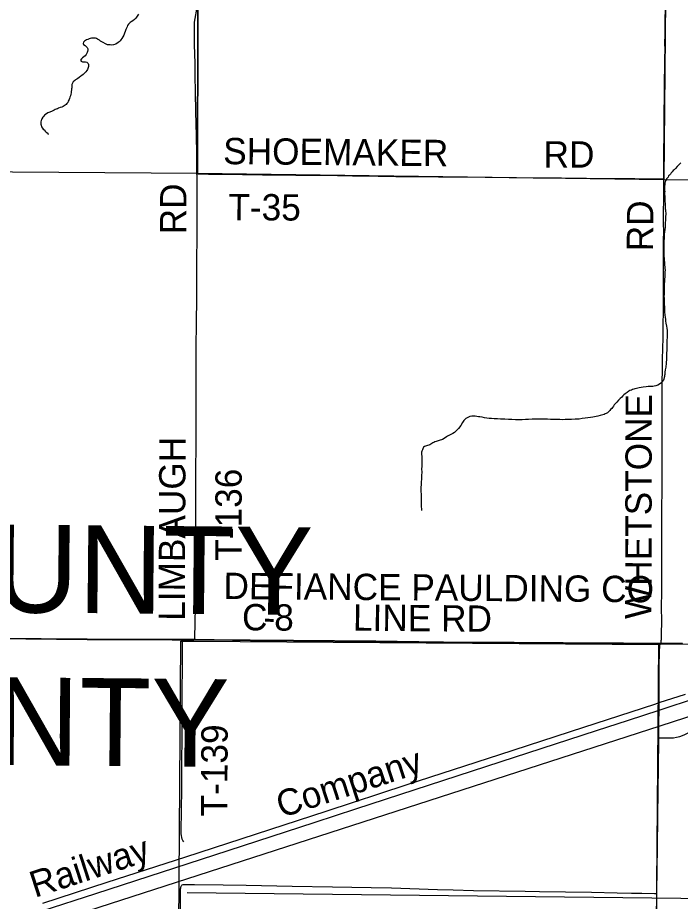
# Model space of a CAD drawing. Extents: x 2.4 to 73.1, y 4.5 to 25.6.
# Drawn here: x 32.327 to 33.042, y 21.341 to 22.294 of the extents above; entities that cross this region are included whole.
import ezdxf

# ---------------------------------------------------------------- set-up
doc = ezdxf.new("R2010")
doc.units = 0
for name, color, linetype in [('GM_X_County_Road', 7, 'Continuous'), ('GM_X_County_Road_Text', 7, 'Continuous'), ('GM_X_County_Text', 7, 'Continuous'), ('GM_X_Minor_River', 7, 'Continuous'), ('GM_X_Rail_Line', 7, 'Continuous'), ('GM_X_Rail_Line_Text', 7, 'Continuous'), ('GM_X_Section', 7, 'Continuous'), ('GM_X_Township', 7, 'Continuous'), ('GM_X_Township_Road', 7, 'Continuous'), ('GM_X_Township_Road_Text', 7, 'Continuous'), ('GM_X_US_Route', 7, 'Continuous'), ('SH_Cut_Line', 7, 'Continuous')]:
    doc.layers.add(name, color=color, linetype=linetype)

msp = doc.modelspace()

# ---------------------------------------------------------------- linework, layer by layer
at = {"layer": 'GM_X_County_Road'}
msp.add_line((32.5052, 21.6229), (32.51811, 21.62282), dxfattribs=at)
for points in [[(33.02436, 22.12034), (33.02435, 22.12228), (33.02437, 22.13408), (33.02432, 22.14061), (33.02442, 22.15305), (33.02456, 22.16455), (33.02467, 22.17729), (33.02486, 22.19159), (33.02497, 22.20899), (33.02506, 22.21676), (33.02509, 22.22547), (33.02538, 22.24101), (33.02561, 22.25531), (33.02561, 22.25996), (33.02559, 22.26618), (33.02573, 22.27613), (33.02582, 22.28514), (33.02609, 22.31001), (33.02646, 22.33395), (33.02651, 22.34203), (33.02657, 22.34887), (33.02658, 22.3585), (33.02647, 22.37223), (33.02645, 22.37476)], [(33.02085, 21.61856), (33.02097, 21.61901), (33.0213, 21.62051), (33.02154, 21.62192), (33.02169, 21.62326), (33.0218, 21.62533), (33.02184, 21.62862), (33.02203, 21.64323), (33.02198, 21.65753), (33.02217, 21.67494), (33.02225, 21.69608), (33.02228, 21.71131), (33.02207, 21.73339), (33.02222, 21.748), (33.02226, 21.76478), (33.02247, 21.78437), (33.02247, 21.79245), (33.02244, 21.8052), (33.0224, 21.81452), (33.02238, 21.82416), (33.02238, 21.83162), (33.02252, 21.85401), (33.02245, 21.86613), (33.02262, 21.90157), (33.02283, 21.91338), (33.02298, 21.92551), (33.02351, 21.94851), (33.02365, 21.96063), (33.02382, 21.97928), (33.02382, 21.99421), (33.02396, 22.02467), (33.02397, 22.03524), (33.02388, 22.0483), (33.02396, 22.05327), (33.02417, 22.06415), (33.02404, 22.07161), (33.02415, 22.08311), (33.0243, 22.09896), (33.02445, 22.10891), (33.02438, 22.11482), (33.02436, 22.12034)], [(32.51811, 21.62282), (32.51929, 21.62281), (32.53949, 21.62262), (32.57836, 21.62213), (32.625, 21.62167), (32.71362, 21.62098), (32.76026, 21.62025), (32.78669, 21.6199), (32.81778, 21.61967), (32.86287, 21.61955), (32.88463, 21.61933), (32.91572, 21.61916), (32.93749, 21.61892), (32.96236, 21.61886), (32.98102, 21.61887), (33.01651, 21.61863), (33.02085, 21.61856)], [(33.01916, 21.54701), (33.01916, 21.54756), (33.01921, 21.55501), (33.01943, 21.59265), (33.01984, 21.61131), (33.0199, 21.61496), (33.02001, 21.61612), (33.02014, 21.61687), (33.02038, 21.61765), (33.02085, 21.61856)], [(33.02085, 21.61856), (33.02249, 21.61855), (33.04476, 21.61844), (33.1054, 21.61773), (33.13457, 21.61727)], [(33.01906, 21.51698), (33.01908, 21.5258), (33.01907, 21.53357), (33.01916, 21.54701)], [(33.01681, 21.3492), (33.01713, 21.3766), (33.01745, 21.39836), (33.01799, 21.43254), (33.01905, 21.51337), (33.01906, 21.51698)], [(33.01432, 21.09649), (33.01438, 21.10239), (33.01506, 21.16984), (33.01564, 21.23513), (33.01595, 21.26623), (33.01616, 21.28954), (33.01639, 21.31286), (33.01681, 21.3492)]]:
    msp.add_lwpolyline(points, dxfattribs=at)
at = {"layer": 'GM_X_Minor_River'}
for points in [[(32.45759, 22.29787), (32.45463, 22.29339), (32.45326, 22.2919), (32.45171, 22.29061), (32.44978, 22.28952), (32.44862, 22.28879), (32.44765, 22.28787), (32.44687, 22.28694), (32.44569, 22.28545), (32.44528, 22.28432), (32.44467, 22.28281), (32.44387, 22.28113), (32.44326, 22.27924), (32.44245, 22.27736), (32.44183, 22.27529), (32.44083, 22.27342), (32.43983, 22.27154), (32.43866, 22.27005), (32.43787, 22.26912), (32.43671, 22.26801), (32.43555, 22.26709), (32.43304, 22.26564), (32.43055, 22.26475), (32.42864, 22.26442), (32.42713, 22.26465), (32.42431, 22.26462)], [(32.42431, 22.26462), (32.41751, 22.26829), (32.41676, 22.26868), (32.41563, 22.26965), (32.41431, 22.27043), (32.41337, 22.27101), (32.41242, 22.27141), (32.41129, 22.27181), (32.40977, 22.27183), (32.40844, 22.27185), (32.40692, 22.27188), (32.40558, 22.27152), (32.40443, 22.27115), (32.40309, 22.27061), (32.40156, 22.27006), (32.4006, 22.26932), (32.39945, 22.26857), (32.39829, 22.26764), (32.39808, 22.26612), (32.39844, 22.26498), (32.39994, 22.26401), (32.40107, 22.26304), (32.40219, 22.26169), (32.40293, 22.26054), (32.40291, 22.25921), (32.4027, 22.2575), (32.4023, 22.25656), (32.40191, 22.25561), (32.40132, 22.25448), (32.39996, 22.25279), (32.3988, 22.25186), (32.39726, 22.25056), (32.39611, 22.24963), (32.39513, 22.24831), (32.39587, 22.24697), (32.3972, 22.24657), (32.39815, 22.24655), (32.39967, 22.24653), (32.40062, 22.24651), (32.40195, 22.24611), (32.40325, 22.24457), (32.40381, 22.24342), (32.40378, 22.24152), (32.40258, 22.23831), (32.40181, 22.23718), (32.40083, 22.23568), (32.39948, 22.23418), (32.39793, 22.23269), (32.39658, 22.23157), (32.39543, 22.23082), (32.39369, 22.22933), (32.39216, 22.22841), (32.39101, 22.22767), (32.38985, 22.22692), (32.38889, 22.22637), (32.38735, 22.22487), (32.38637, 22.22337), (32.38578, 22.22186), (32.38556, 22.21977), (32.38573, 22.21844), (32.38552, 22.2173), (32.3853, 22.21559), (32.3851, 22.21465), (32.38488, 22.21313), (32.38467, 22.21162), (32.38426, 22.20972), (32.38366, 22.20821), (32.38326, 22.20689), (32.38286, 22.20575), (32.38188, 22.20387), (32.38129, 22.20255), (32.38032, 22.20142), (32.37955, 22.20049), (32.37839, 22.19956), (32.37743, 22.19881), (32.37628, 22.19807), (32.37494, 22.19752), (32.37322, 22.19698), (32.3715, 22.19624), (32.37015, 22.1957), (32.36882, 22.19534), (32.36767, 22.19497), (32.36652, 22.19442), (32.36441, 22.19332), (32.36192, 22.19222), (32.35982, 22.19149), (32.35731, 22.18944), (32.35635, 22.18869), (32.35558, 22.18776), (32.35442, 22.18663), (32.35344, 22.18494), (32.35304, 22.184), (32.35265, 22.18305), (32.35225, 22.18154), (32.35223, 22.1804), (32.3524, 22.17907), (32.35257, 22.17792), (32.35311, 22.1762), (32.35423, 22.17486), (32.35498, 22.1739), (32.35591, 22.17293)], [(32.35591, 22.17293), (32.35704, 22.17177), (32.35816, 22.17061), (32.3591, 22.16965), (32.36022, 22.1683), (32.36041, 22.1683)], [(33.04275, 22.1376), (33.04176, 22.13629), (33.04021, 22.13481), (33.03865, 22.13333), (33.03709, 22.13147), (33.03534, 22.13), (33.03437, 22.12926), (33.03319, 22.12758), (33.03221, 22.12647), (33.03142, 22.12516), (33.03044, 22.12404), (33.02947, 22.12331), (33.02887, 22.122), (33.0279, 22.12107), (33.02731, 22.12014), (33.0269, 22.1192), (33.0263, 22.11807), (33.0259, 22.11713), (33.02548, 22.11563), (33.02526, 22.11411), (33.02521, 22.11221), (33.0251, 22.10804), (33.02526, 22.10652), (33.02523, 22.10557), (33.02521, 22.10462), (33.02518, 22.10329), (33.02532, 22.10157), (33.02547, 22.10005), (33.02542, 22.09797), (33.02556, 22.09587), (33.02569, 22.09359), (33.02583, 22.09131), (33.02578, 22.0896), (33.02593, 22.08789), (33.02609, 22.08655), (33.02624, 22.08503), (33.02639, 22.08332), (33.02634, 22.08161), (33.0263, 22.0799), (33.02626, 22.07819), (33.02622, 22.07667), (33.02599, 22.07497), (33.02595, 22.07345), (33.02571, 22.07156), (33.02567, 22.06966), (33.02562, 22.06795), (33.02537, 22.0653), (33.02512, 22.06303), (33.02487, 22.06057), (33.02481, 22.0581), (33.02455, 22.05564), (33.02449, 22.05317), (33.02444, 22.05089), (33.02419, 22.04843), (33.02433, 22.04653), (33.02427, 22.04406), (33.02439, 22.04159), (33.02434, 22.03931), (33.02446, 22.03646), (33.0246, 22.03475), (33.02457, 22.03342), (33.02472, 22.03189), (33.02488, 22.03056), (33.02503, 22.02885), (33.02517, 22.02694), (33.02532, 22.02523), (33.02546, 22.02352), (33.0256, 22.02162), (33.02537, 22.01972), (33.02549, 22.01706), (33.02511, 22.00928), (33.02485, 22.00663), (33.02478, 22.00398), (33.02472, 22.00151), (33.02465, 21.99866), (33.02458, 21.99581), (33.02451, 21.99316), (33.02466, 21.99125), (33.02479, 21.98916), (33.02473, 21.98669), (33.02487, 21.98441), (33.02501, 21.9827), (33.02496, 21.98061)], [(33.02496, 21.98061), (33.0251, 21.97871), (33.02504, 21.97624), (33.02535, 21.97338), (33.02566, 21.97072), (33.026, 21.96881), (33.02613, 21.96672), (33.02665, 21.96443), (33.02714, 21.96138), (33.02765, 21.95889), (33.02797, 21.95661), (33.02811, 21.95451), (33.02806, 21.95262), (33.02801, 21.95053), (33.02777, 21.94845), (33.02772, 21.94655), (33.02766, 21.94408), (33.0276, 21.9418), (33.02754, 21.93953), (33.0275, 21.93763), (33.02742, 21.93478), (33.02738, 21.93288), (33.02733, 21.93099), (33.02727, 21.92871), (33.02721, 21.92605), (33.0269, 21.92131), (33.02641, 21.91695), (33.02595, 21.91393), (33.02551, 21.91147), (33.02527, 21.9092), (33.02504, 21.90787), (33.02501, 21.90674), (33.02461, 21.9058), (33.02419, 21.9041), (33.02357, 21.90221), (33.0226, 21.9011), (33.02123, 21.89961), (33.01949, 21.89852), (33.01775, 21.89742), (33.01565, 21.89672), (33.01393, 21.89638), (33.0126, 21.89622), (33.01165, 21.89625), (33.01051, 21.89628), (33.00917, 21.89612), (33.00746, 21.89597), (33.00517, 21.89565), (33.00194, 21.89535), (32.99984, 21.89503), (32.99774, 21.8947), (32.99622, 21.89436), (32.99488, 21.89401), (32.99316, 21.89368), (32.99182, 21.89314), (32.99067, 21.89279), (32.98933, 21.89226), (32.98779, 21.89172), (32.98664, 21.89099), (32.9847, 21.88952), (32.98277, 21.88824), (32.98122, 21.88714), (32.98025, 21.88622), (32.97888, 21.88473), (32.97713, 21.88307), (32.97538, 21.88121), (32.97381, 21.87935), (32.97225, 21.87768), (32.97088, 21.8762), (32.9699, 21.8749), (32.96911, 21.87359), (32.96813, 21.87247), (32.96696, 21.87117), (32.96598, 21.87006), (32.96481, 21.86895), (32.96345, 21.86765), (32.9623, 21.86711), (32.96115, 21.86657), (32.9598, 21.86604), (32.95559, 21.86481), (32.9533, 21.86411), (32.94776, 21.86311), (32.94529, 21.86279), (32.93957, 21.86199), (32.93633, 21.86169), (32.93309, 21.86101), (32.92853, 21.86094), (32.92472, 21.86066), (32.9213, 21.86055), (32.91788, 21.86045), (32.91502, 21.86014), (32.91199, 21.86041), (32.90876, 21.86049), (32.90535, 21.86058), (32.90193, 21.86066), (32.8989, 21.86093), (32.89605, 21.861), (32.89225, 21.86091), (32.88921, 21.86098), (32.88541, 21.86089), (32.88219, 21.86097), (32.87838, 21.86069)], [(32.87838, 21.86069), (32.87495, 21.8604), (32.87134, 21.8603), (32.86792, 21.86019), (32.86432, 21.86028), (32.86052, 21.86038), (32.85672, 21.86048), (32.85293, 21.86076), (32.84819, 21.86088), (32.84477, 21.86116), (32.84136, 21.86125), (32.83833, 21.86151), (32.83586, 21.86176), (32.8334, 21.86202), (32.83094, 21.86246), (32.82829, 21.8629), (32.82603, 21.86334), (32.82451, 21.86357), (32.82262, 21.86381), (32.82073, 21.86405), (32.81978, 21.86407), (32.81845, 21.8641), (32.81711, 21.86395), (32.81521, 21.86362), (32.81367, 21.86308), (32.81214, 21.86236), (32.81078, 21.86145), (32.80962, 21.86053), (32.80864, 21.85941), (32.80726, 21.85717), (32.80528, 21.85399), (32.80292, 21.85063), (32.79864, 21.84656), (32.79671, 21.84528), (32.79459, 21.8442), (32.79093, 21.84239), (32.78997, 21.84165), (32.78842, 21.84074), (32.78572, 21.8391), (32.78189, 21.83768), (32.77883, 21.83681), (32.77749, 21.83646), (32.77614, 21.83574), (32.77518, 21.83519), (32.77402, 21.83446), (32.77209, 21.83318), (32.76845, 21.83194), (32.76616, 21.83124), (32.76519, 21.83051), (32.76439, 21.82882), (32.76398, 21.82788), (32.76337, 21.82638), (32.76297, 21.82525), (32.76294, 21.82411), (32.7631, 21.82277), (32.76324, 21.82087), (32.7632, 21.81916), (32.76335, 21.81764), (32.7633, 21.81555), (32.76325, 21.81384), (32.7632, 21.81195), (32.76315, 21.80986), (32.76309, 21.80739), (32.76319, 21.80378), (32.7631, 21.80017), (32.76282, 21.79638), (32.76273, 21.79297), (32.76247, 21.79012), (32.76221, 21.78747), (32.76213, 21.78425), (32.76228, 21.78234), (32.76241, 21.78025), (32.76254, 21.77778), (32.76247, 21.77474), (32.76259, 21.77208), (32.76253, 21.76961), (32.76266, 21.76714), (32.76276, 21.76353), (32.76292, 21.76239)], [(32.50998, 21.35024), (33.07394, 21.34372), (33.14382, 21.39998), (33.14632, 21.41556), (33.1498, 21.45015), (33.15704, 21.46115), (33.16712, 21.46493), (33.3527, 21.46383), (33.38617, 21.46621), (33.42042, 21.47866), (33.44591, 21.48372), (33.47044, 21.48441), (33.5127, 21.49167)]]:
    msp.add_lwpolyline(points, dxfattribs=at)
at = {"layer": 'GM_X_Rail_Line'}
msp.add_lwpolyline([(29.49738, 20.38454), (29.78056, 20.47623), (30.02642, 20.55584), (30.5317, 20.7222), (31.06173, 20.89547), (31.60226, 21.07108), (31.99378, 21.19809), (32.24901, 21.28076), (33.02045, 21.53011), (33.27514, 21.61267)], dxfattribs=at)
at = {"layer": 'GM_X_Section'}
for points in [[(32.52237, 22.62648), (32.5213, 22.12602), (32.02184, 22.12942), (32.0257, 22.62946)], [(33.02904, 22.62432), (33.02446, 22.1192), (32.5213, 22.12602), (32.52237, 22.62648)], [(33.5389, 22.62058), (33.53887, 22.61906), (33.53166, 22.11533), (33.02446, 22.1192), (33.02904, 22.62432)], [(32.51749, 21.62129), (33.01863, 21.61775), (33.01442, 21.09688), (32.49959, 21.10721), (32.50347, 21.62138)]]:
    msp.add_lwpolyline(points, close=True, dxfattribs=at)
at = {"layer": 'GM_X_Township'}
msp.add_lwpolyline([(32.30268, 21.62435), (32.40211, 21.6236), (32.45338, 21.62327), (32.49377, 21.62322), (32.50508, 21.62318), (32.51799, 21.62309), (32.51917, 21.62308), (32.53937, 21.6229), (32.57824, 21.6224), (32.62488, 21.62194), (32.7135, 21.62126), (32.76014, 21.62052), (32.78657, 21.62018), (32.81766, 21.61995), (32.86275, 21.61982), (32.88451, 21.6196), (32.91561, 21.61943), (32.93737, 21.61919), (32.96224, 21.61913), (32.9809, 21.61915), (33.01639, 21.61891), (33.02074, 21.61883), (33.02237, 21.61883), (33.04465, 21.61871)], dxfattribs=at)
msp.add_lwpolyline([(32.30268, 21.62435), (32.40211, 21.6236), (32.45338, 21.62327), (32.49377, 21.62322), (32.50508, 21.62318), (32.51799, 21.62309), (32.51917, 21.62308), (32.53937, 21.6229), (32.57824, 21.6224), (32.62488, 21.62194), (32.7135, 21.62126), (32.76014, 21.62052), (32.78657, 21.62018), (32.81766, 21.61995), (32.86275, 21.61982), (32.88451, 21.6196), (32.91561, 21.61943), (32.93737, 21.61919), (32.96224, 21.61913), (32.9809, 21.61915), (33.01639, 21.61891), (33.02074, 21.61883), (33.02237, 21.61883), (33.04465, 21.61871)], dxfattribs=at)
at = {"layer": 'GM_X_Township_Road'}
msp.add_line((32.5052, 21.6229), (32.51811, 21.62282), dxfattribs=at)
for points in [[(32.52073, 22.12551), (32.52061, 22.1333), (32.52042, 22.14698), (32.52005, 22.16656), (32.51945, 22.19297), (32.51923, 22.21348), (32.51887, 22.23213), (32.5187, 22.24487), (32.51823, 22.26475), (32.51807, 22.27439), (32.51797, 22.28309), (32.51807, 22.28713), (32.51823, 22.28929), (32.51872, 22.29298), (32.52041, 22.3031)], [(32.51811, 21.62282), (32.51825, 21.62463), (32.51833, 21.62736), (32.51866, 21.63864), (32.51876, 21.64216), (32.5188, 21.64429), (32.51898, 21.65505), (32.51914, 21.66678), (32.51913, 21.69507), (32.51945, 21.73018), (32.51954, 21.77215), (32.51965, 21.79856), (32.51976, 21.83959), (32.51985, 21.85544), (32.51992, 21.87347), (32.51991, 21.89119), (32.51994, 21.91201), (32.51995, 21.93843), (32.52017, 21.96454), (32.5205, 21.99127), (32.5206, 22.03789), (32.52081, 22.05156), (32.52083, 22.08047), (32.52096, 22.10161), (32.5208, 22.1199)], [(32.52073, 22.12551), (32.5243, 22.12548), (32.52555, 22.12548), (32.53332, 22.12526), (32.54296, 22.12507), (32.57, 22.12478), (32.59146, 22.12458), (32.62721, 22.12419), (32.63592, 22.12412), (32.6468, 22.12409), (32.67229, 22.12367), (32.68846, 22.1235), (32.7012, 22.12331), (32.71612, 22.12322), (32.7354, 22.12287), (32.74908, 22.12269), (32.76649, 22.12256), (32.78142, 22.12248), (32.79323, 22.12236), (32.83178, 22.1219), (32.88339, 22.12132), (32.89738, 22.12126), (32.91386, 22.12115), (32.94091, 22.12094), (32.97324, 22.1206), (32.99314, 22.12049), (33.01211, 22.12028), (33.0205, 22.12032), (33.02436, 22.12034)], [(32.5208, 22.1199), (32.52077, 22.12336), (32.52073, 22.12551)], [(32.01559, 21.62599), (32.04024, 21.62583), (32.05733, 21.62573), (32.08374, 21.62554), (32.10394, 21.62554), (32.14277, 21.62518), (32.17851, 21.62504), (32.20337, 21.62488), (32.24842, 21.62448), (32.2624, 21.62439), (32.2826, 21.62423), (32.3028, 21.62407), (32.40223, 21.62332), (32.4535, 21.623), (32.49389, 21.62295), (32.5052, 21.6229)], [(32.50661, 21.40479), (32.50541, 21.40642), (32.50473, 21.40773), (32.50427, 21.40964), (32.50386, 21.4118), (32.50375, 21.41336), (32.50385, 21.42065), (32.50404, 21.43418), (32.5043, 21.46681), (32.50439, 21.49324), (32.50459, 21.515), (32.50463, 21.54763), (32.50482, 21.56006), (32.50507, 21.60047), (32.5052, 21.6229)], [(32.51811, 21.62282), (32.51929, 21.62281), (32.53949, 21.62262), (32.57836, 21.62213), (32.625, 21.62167), (32.71362, 21.62098), (32.76026, 21.62025), (32.78669, 21.6199), (32.81778, 21.61967), (32.86287, 21.61955), (32.88463, 21.61933), (32.91572, 21.61916), (32.93749, 21.61892), (32.96236, 21.61886), (32.98102, 21.61887), (33.01651, 21.61863), (33.02085, 21.61856)], [(33.01906, 21.51698), (33.0225, 21.51698), (33.03181, 21.51699), (33.03488, 21.51721), (33.03791, 21.51765), (33.04177, 21.51862), (33.04637, 21.52038), (33.05131, 21.52292), (33.05985, 21.52798), (33.06978, 21.53383), (33.0764, 21.53734), (33.08233, 21.54012), (33.08837, 21.54263), (33.09627, 21.54552), (33.11635, 21.55218), (33.15567, 21.56499), (33.2553, 21.59744), (33.28546, 21.60725), (33.29385, 21.60965), (33.30113, 21.61141), (33.30848, 21.61279), (33.31528, 21.6137), (33.32274, 21.61432), (33.33053, 21.61456)], [(33.02085, 21.61856), (33.02249, 21.61855), (33.04476, 21.61844), (33.1054, 21.61773), (33.13457, 21.61727)], [(32.50074, 21.10816), (32.50069, 21.11094), (32.50136, 21.15601), (32.50145, 21.17311), (32.50189, 21.21973), (32.50222, 21.24304), (32.50216, 21.24926), (32.50236, 21.2679), (32.50276, 21.28811), (32.50295, 21.31142), (32.50305, 21.33784), (32.50305, 21.35248), (32.50307, 21.35327), (32.5031, 21.35415), (32.50318, 21.35529), (32.50326, 21.3562), (32.50352, 21.35695), (32.50393, 21.35756)], [(32.50393, 21.35756), (32.50436, 21.35805), (32.50487, 21.35843), (32.50566, 21.35871), (32.50653, 21.35878), (32.50862, 21.35879), (32.51793, 21.35866), (32.54896, 21.35855), (32.57379, 21.35809), (32.62344, 21.35687), (32.66688, 21.35631), (32.70878, 21.35548), (32.7305, 21.35514), (32.78014, 21.3536), (32.79719, 21.35293), (32.81891, 21.35221), (32.87477, 21.35149), (32.89029, 21.35123), (32.91822, 21.35094), (32.94615, 21.35039), (32.97407, 21.34966), (32.98959, 21.34942), (33.00045, 21.34945), (33.01441, 21.34924), (33.01681, 21.3492)]]:
    msp.add_lwpolyline(points, dxfattribs=at)
at = {"layer": 'GM_X_US_Route'}
for points in [[(32.35363, 21.33033), (32.41155, 21.34922), (32.55434, 21.39562), (32.64833, 21.42624), (32.69207, 21.44047), (32.724, 21.45084), (32.83338, 21.4864), (32.95188, 21.52506), (32.98617, 21.53622), (33.01916, 21.54701), (33.03344, 21.55168), (33.12659, 21.58187)], [(32.35445, 21.33859), (32.42392, 21.36119), (32.46617, 21.375), (32.50874, 21.38884), (32.66009, 21.43808), (32.74757, 21.46659), (32.84748, 21.49912), (32.93821, 21.52867), (33.01449, 21.55346), (33.01921, 21.55501), (33.04757, 21.56429)]]:
    msp.add_lwpolyline(points, dxfattribs=at)
at = {"layer": 'SH_Cut_Line'}
for points in [[(33.04465, 21.61871), (33.02237, 21.61883), (33.02074, 21.61883), (33.01639, 21.61891), (32.9809, 21.61915), (32.96224, 21.61913), (32.93737, 21.61919), (32.91561, 21.61943), (32.88451, 21.6196), (32.86275, 21.61982), (32.81766, 21.61995), (32.78657, 21.62018), (32.76014, 21.62052), (32.7135, 21.62126), (32.62488, 21.62194), (32.57824, 21.6224), (32.53937, 21.6229), (32.51917, 21.62308), (32.51799, 21.62309), (32.50508, 21.62318), (32.49377, 21.62322), (32.45338, 21.62327), (32.40211, 21.6236), (32.30268, 21.62435)], [(32.30268, 21.62435), (32.40211, 21.6236), (32.45338, 21.62327), (32.49377, 21.62322), (32.50508, 21.62318), (32.51799, 21.62309), (32.51917, 21.62308), (32.53937, 21.6229), (32.57824, 21.6224), (32.62488, 21.62194), (32.7135, 21.62126), (32.76014, 21.62052), (32.78657, 21.62018), (32.81766, 21.61995), (32.86275, 21.61982), (32.88451, 21.6196), (32.91561, 21.61943), (32.93737, 21.61919), (32.96224, 21.61913), (32.9809, 21.61915), (33.01639, 21.61891), (33.02074, 21.61883), (33.02237, 21.61883), (33.04465, 21.61871)]]:
    msp.add_lwpolyline(points, dxfattribs=at)

# ---------------------------------------------------------------- texts
at = {"layer": 'GM_X_County_Road_Text'}
for s, height, rotation, p in [('RD', 0.028409, 89.51079, (33.01265, 22.04189)), ('WHETSTONE', 0.028409, 89.88753, (33.01097, 21.64528)), ('DEFIANCE PAULDING CO', 0.0284091, 359.54135, (32.54926, 21.6669)), ('C', 0.02841, 359.44721, (32.5692, 21.63315)), ('8', 0.02841, 359.47992, (32.60394, 21.63283)), ('LINE RD', 0.028409, 359.47274, (32.6889, 21.63271)), ('-', 0.02841, 359.47732, (32.59238, 21.63293))]:
    msp.add_text(s, height=height, rotation=rotation, dxfattribs=at).set_placement(p)
at = {"layer": 'GM_X_County_Text'}
for s, p in [('DEFIANCE COUNTY', (31.43551, 21.6602)), ('PAULDING COUNTY', (31.33808, 21.4963))]:
    msp.add_text(s, height=0.094697, rotation=359.49363, dxfattribs=at).set_placement(p)
at = {"layer": 'GM_X_Rail_Line_Text'}
for s, rotation, p in [('Company', 17.93158, (32.61179, 21.43047)), ('Railway', 17.94561, (32.3459, 21.34438))]:
    msp.add_text(s, height=0.028314, rotation=rotation, dxfattribs=at).set_placement(p)
at = {"layer": 'GM_X_Township_Road_Text'}
for s, rotation, p in [('SHOEMAKER', 359.45069, (32.54891, 22.13605)), ('RD', 0.00001, (32.89465, 22.1323)), ('RD', 90, (32.50931, 22.06029)), ('T-35', 359.64634, (32.55454, 22.07557)), ('LIMBAUGH', 89.74616, (32.50763, 21.64333)), ('T-136', 90, (32.56896, 21.70821)), ('T-139', 89.71922, (32.55341, 21.43224))]:
    msp.add_text(s, height=0.028409, rotation=rotation, dxfattribs=at).set_placement(p)

doc.saveas('drawing.dxf')
